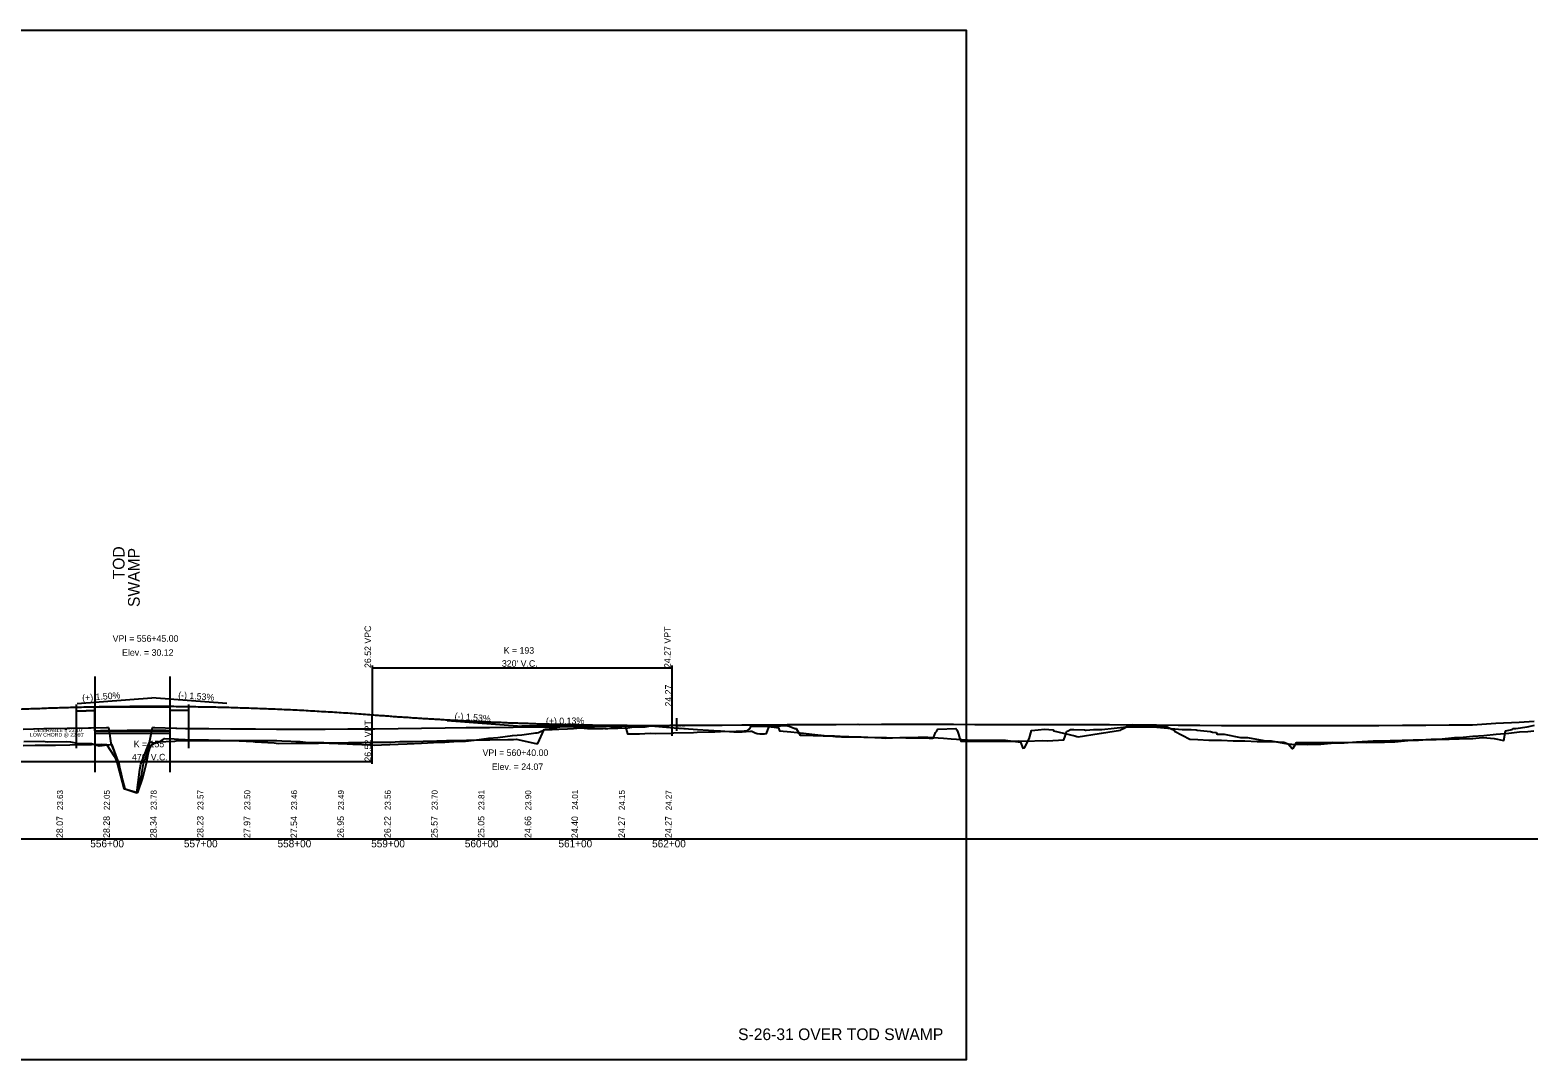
# Model space of a CAD drawing. Extents: x 2651734 to 2654815, y 758274 to 759374.
# Drawn here: x 2653205 to 2654815, y 758274 to 759374 of the extents above; entities that cross this region are included whole.
import ezdxf

# ---------------------------------------------------------------- set-up
doc = ezdxf.new("R2010")
doc.units = 0
for name, color, linetype in [('BR_CONCRETE', 7, 'Continuous'), ('BR_EXIST_GROUND_RT', 7, 'Continuous'), ('RD_EX_H2O_txCode', 7, 'Continuous'), ('RD_PD_CstnLmt', 7, 'Continuous'), ('RD_PD_DR_ErosCtrl', 7, 'Continuous'), ('RD_PD_Final_TrvlWay', 7, 'Continuous'), ('RD_PD_PaveShd', 7, 'Continuous'), ('RD_PD_RW_TX', 7, 'Continuous'), ('RD_SHT_IplotShp', 7, 'Continuous'), ('RD_SHT_ShtClip', 7, 'Continuous'), ('RD_SHT_TX', 7, 'Continuous'), ('RD_Sketch8', 7, 'Continuous')]:
    doc.layers.add(name, color=color, linetype=linetype)

msp = doc.modelspace()

# ---------------------------------------------------------------- linework, layer by layer
at = {"layer": 'BR_CONCRETE'}
for p, q in [((2653253.9, 758650.7), (2653253.9, 758646.7)), ((2653273.9, 758651.1), (2653273.9, 758625.4)), ((2653353.9, 758651.6), (2653353.9, 758625.9)), ((2653373.9, 758651.4), (2653373.9, 758647.4))]:
    msp.add_line(p, q, dxfattribs=at)
msp.add_lwpolyline([(2653197.2, 758627.3), (2653219.4, 758627.7), (2653222.2, 758627.8), (2653244.2, 758628.2), (2653247.2, 758628.2), (2653267.2, 758628.6), (2653270.1, 758628.6), (2653286.5, 758629), (2653288.5, 758629.1), (2653288.8, 758627.5), (2653291.1, 758612.1), (2653297.8, 758594.9), (2653299.3, 758590.8), (2653301.1, 758583.6), (2653305.4, 758563.5), (2653311.8, 758561.5), (2653319.2, 758559.4), (2653323.8, 758577.6), (2653325.7, 758590.5), (2653329.3, 758599.5), (2653332.2, 758612.9), (2653335.3, 758628.9), (2653338.1, 758628.9), (2653360.3, 758628.2), (2653361.4, 758628.2), (2653370.6, 758627.9), (2653393.4, 758627.8), (2653395.6, 758627.7), (2653418.6, 758627.6), (2653420.6, 758627.5), (2653443.9, 758627.4), (2653445.6, 758627.4), (2653467.9, 758627.2), (2653469.2, 758627.2), (2653470.6, 758627.2), (2653494.2, 758627.3), (2653495.3, 758627.3), (2653519.2, 758627.3), (2653520, 758627.3), (2653544.2, 758627.4), (2653544.7, 758627.4), (2653569.2, 758627.5), (2653572.9, 758627.5), (2653597.9, 758627.8), (2653622.9, 758628.2), (2653647.9, 758628.5), (2653670.5, 758628.8), (2653693.5, 758629), (2653695.5, 758629), (2653720.7, 758629.3), (2653745.5, 758629.5), (2653745.9, 758629.5), (2653769.9, 758629.7), (2653770.4, 758629.7), (2653794.9, 758630), (2653819.5, 758630.4), (2653819.9, 758630.4), (2653844.6, 758630.8), (2653844.9, 758630.8), (2653868.5, 758631.1), (2653893.2, 758631.3), (2653893.6, 758631.3), (2653918.2, 758631.5), (2653918.7, 758631.5), (2653943.2, 758631.6), (2653943.8, 758631.6), (2653964.7, 758631.8), (2653988.7, 758631.9), (2653989.7, 758631.9), (2654013.4, 758632), (2654014.7, 758632.1), (2654015.4, 758632.1), (2654038.9, 758632.2), (2654040.5, 758632.2), (2654063, 758632.3), (2654063.8, 758632.3), (2654065.6, 758632.3), (2654088.8, 758632.4), (2654090.6, 758632.3), (2654113.8, 758632.4), (2654115.6, 758632.4), (2654138.8, 758632.4), (2654140.6, 758632.4), (2654163.8, 758632.4), (2654165.5, 758632.4), (2654188.8, 758632.4), (2654190.8, 758632.4), (2654213.8, 758632.3), (2654216, 758632.3), (2654238.8, 758632.2), (2654241.1, 758632.2), (2654261.4, 758632.2), (2654264.2, 758632.2), (2654286.4, 758632.2), (2654289, 758632.2), (2654311.4, 758632.2), (2654313.8, 758632.2), (2654336.4, 758632.2), (2654338.2, 758632.2), (2654356.5, 758632.2), (2654357.4, 758632.2), (2654380.4, 758631.9), (2654382.4, 758632), (2654405.5, 758631.8), (2654405.8, 758631.8), (2654407.7, 758631.7), (2654430.8, 758631.5), (2654431.2, 758631.5), (2654433.1, 758631.5), (2654452, 758631.3), (2654453.9, 758631.3), (2654477, 758631.2), (2654478.2, 758631.2), (2654502, 758631.1), (2654502.6, 758631.1), (2654521.4, 758631.1), (2654527.1, 758631), (2654548.5, 758630.9), (2654549.2, 758630.9), (2654573.5, 758631), (2654574, 758631), (2654598.5, 758631), (2654598.9, 758631), (2654623.5, 758631.1), (2654645.2, 758631.1), (2654670.2, 758631.3), (2654695.2, 758631.5), (2654720.2, 758631.7), (2654745, 758631.9), (2654770, 758633.4), (2654794.9, 758634.8), (2654811.1, 758635.8)], dxfattribs=at)
for points, degree in [([(2653253.9, 758646.7), (2653260.6, 758646.8), (2653267.2, 758647), (2653273.9, 758647.1)], 2), ([(2653353.9, 758647.6), (2653360.6, 758647.5), (2653367.2, 758647.4), (2653373.9, 758647.4)], 2), ([(2653273.9, 758625.4), (2653274.8, 758625.5), (2653275.7, 758625.5), (2653296, 758625.8), (2653315.4, 758626), (2653341.2, 758626), (2653347.6, 758626), (2653353.9, 758625.9)], 3)]:
    msp.add_open_spline(points, degree=degree, dxfattribs=at)
at = {"layer": 'BR_EXIST_GROUND_RT'}
msp.add_lwpolyline([(2653197.9, 758614), (2653218.8, 758614.2), (2653222.9, 758613.8), (2653243.4, 758613.9), (2653247.9, 758613.5), (2653256.5, 758612), (2653270.3, 758612), (2653278.6, 758609.5), (2653281.6, 758609.8), (2653286.7, 758610.4), (2653294.5, 758598.2), (2653296.3, 758594.8), (2653297.3, 758592), (2653297.9, 758589.3), (2653304.9, 758563.6), (2653314.6, 758560.8), (2653319.7, 758559.4), (2653325, 758575.3), (2653329.2, 758591), (2653331.2, 758602.1), (2653333.6, 758610.2), (2653340.6, 758613.8), (2653359.3, 758614.3), (2653360.7, 758614.8), (2653370.5, 758615), (2653374, 758615), (2653395.3, 758615), (2653399.2, 758615), (2653420.2, 758615.1), (2653424.5, 758615), (2653445.1, 758615.1), (2653449.7, 758615), (2653467.4, 758615), (2653468.3, 758615), (2653473.6, 758614.6), (2653493.3, 758613.9), (2653498.8, 758613.4), (2653518.3, 758612.8), (2653524.1, 758612.2), (2653543.3, 758611.6), (2653549.5, 758611), (2653568.2, 758610.4), (2653569.5, 758610.3), (2653572.9, 758610.2), (2653580, 758610.5), (2653597.9, 758611.1), (2653607.5, 758611.6), (2653622.8, 758612.2), (2653635.5, 758612.9), (2653647.7, 758613.4), (2653662, 758614.2), (2653669.8, 758614.5), (2653679, 758615.4), (2653694.8, 758617.4), (2653704.3, 758618.3), (2653719.8, 758620.3), (2653729.7, 758621.1), (2653744.8, 758623.2), (2653746.4, 758623.4), (2653747.7, 758623.5), (2653755, 758627.1), (2653762.6, 758628), (2653770.1, 758629.6), (2653777.8, 758630.7), (2653791.3, 758630.1), (2653791.8, 758630.2), (2653792.8, 758629.6), (2653796.5, 758628.5), (2653818.6, 758627.9), (2653821.2, 758628), (2653821.6, 758628), (2653842.9, 758628.7), (2653847.2, 758629.2), (2653861.5, 758629.8), (2653867.6, 758630.6), (2653884.3, 758629.4), (2653892.4, 758628.7), (2653913, 758627.3), (2653917.3, 758626.9), (2653940.8, 758625.4), (2653942.2, 758625.3), (2653956.1, 758624.3), (2653965.3, 758624.3), (2653974.1, 758625.1), (2653975.4, 758625), (2653978.9, 758623.2), (2653981.1, 758622.7), (2653984.2, 758622), (2653989.2, 758622.1), (2653991.2, 758622.4), (2653993.6, 758629.2), (2653994.5, 758630.2), (2654000.3, 758630.3), (2654011.9, 758631.1), (2654015.2, 758630.5), (2654021.4, 758628), (2654022.7, 758627.8), (2654027, 758620.8), (2654030.4, 758620.7), (2654051.8, 758620.2), (2654054.8, 758620.1), (2654063.7, 758619.9), (2654069.8, 758619.7), (2654088.7, 758618.9), (2654092.1, 758618.8), (2654113.8, 758617.8), (2654114.3, 758617.8), (2654118.3, 758617.6), (2654133.7, 758618.1), (2654138.8, 758618.2), (2654153.1, 758618.5), (2654163.4, 758618.7), (2654180.3, 758617.5), (2654188.3, 758617), (2654211.5, 758615.3), (2654213.3, 758615.3), (2654235.7, 758615.3), (2654238.3, 758615.3), (2654243.2, 758615.4), (2654246.3, 758615.4), (2654262.4, 758613.4), (2654265, 758606.7), (2654266.7, 758607.2), (2654271.5, 758616.8), (2654274.3, 758625.7), (2654281.3, 758626.5), (2654288.2, 758627.1), (2654297.3, 758626.5), (2654297.7, 758625.5), (2654320.3, 758619.9), (2654322.6, 758619.3), (2654323.9, 758619), (2654346.4, 758622.5), (2654348.8, 758622.9), (2654369.2, 758626.1), (2654369.8, 758626.7), (2654373.1, 758628.3), (2654375.9, 758629.9), (2654384.2, 758630), (2654394.1, 758631.3), (2654396.7, 758631.4), (2654403.3, 758630.6), (2654417.4, 758630), (2654418.2, 758630), (2654422.7, 758627.9), (2654426.6, 758626.1), (2654426.9, 758625), (2654443.3, 758616.5), (2654451.9, 758616), (2654463.7, 758615.5), (2654476.9, 758615.4), (2654489.4, 758614.8), (2654501.9, 758614.7), (2654515.3, 758614.1), (2654526.9, 758614), (2654532, 758613.9), (2654543.5, 758613.3), (2654548.2, 758611.5), (2654552.5, 758606.5), (2654553.2, 758606.5), (2654553.6, 758606.9), (2654557.2, 758612.8), (2654569.8, 758613), (2654582.2, 758612.8), (2654595.3, 758613.1), (2654607.1, 758612.9), (2654620.7, 758613.2), (2654632, 758613), (2654643.5, 758613.2), (2654651.1, 758613.1), (2654662.1, 758613.6), (2654676.1, 758614.9), (2654687.4, 758615.4), (2654701, 758616.6), (2654712.7, 758617), (2654726, 758618.2), (2654735.3, 758618.6), (2654745.4, 758619.5), (2654757.3, 758620.4), (2654770.4, 758621.9), (2654783.8, 758622.9), (2654795.4, 758624.2), (2654804.1, 758624.8), (2654810.5, 758625.5)], dxfattribs=at)
at = {"layer": 'RD_EX_H2O_txCode'}
msp.add_line((2651814.9, 758509.9), (2654814.9, 758509.9), dxfattribs=at)
at = {"layer": 'RD_PD_DR_ErosCtrl'}
for points in [[(2653099.9, 758643), (2653109.3, 758643.7), (2653118.7, 758644.3), (2653128.1, 758644.9), (2653137.5, 758645.5), (2653146.9, 758646.1), (2653156.3, 758646.7), (2653165.7, 758647.2), (2653175.1, 758647.7), (2653184.5, 758648.1), (2653193.9, 758648.6), (2653203.3, 758649), (2653212.7, 758649.3), (2653222.1, 758649.7), (2653231.5, 758650), (2653240.9, 758650.3), (2653250.3, 758650.6), (2653259.7, 758650.8), (2653269.1, 758651), (2653278.5, 758651.2), (2653287.9, 758651.3), (2653297.3, 758651.4), (2653306.7, 758651.5), (2653316.1, 758651.6), (2653325.5, 758651.6), (2653334.9, 758651.6), (2653344.3, 758651.6), (2653353.7, 758651.6), (2653363.1, 758651.5), (2653372.5, 758651.4), (2653381.9, 758651.2), (2653391.3, 758651.1), (2653400.7, 758650.9), (2653410.1, 758650.7), (2653419.5, 758650.4), (2653428.9, 758650.1), (2653438.3, 758649.8), (2653447.7, 758649.5), (2653457.1, 758649.1), (2653466.5, 758648.7), (2653475.9, 758648.3), (2653485.3, 758647.9), (2653494.7, 758647.4), (2653504.1, 758646.9), (2653513.5, 758646.3), (2653522.9, 758645.8), (2653532.3, 758645.2), (2653541.7, 758644.6), (2653551.1, 758643.9), (2653560.5, 758643.2), (2653569.9, 758642.5)], [(2653569.9, 758642.5), (2653576.3, 758642), (2653582.7, 758641.6), (2653589.1, 758641.1), (2653595.5, 758640.6), (2653601.9, 758640.2), (2653608.3, 758639.8), (2653614.7, 758639.3), (2653621.1, 758638.9), (2653627.5, 758638.5), (2653633.9, 758638.1), (2653640.3, 758637.8), (2653646.7, 758637.4), (2653653.1, 758637), (2653659.5, 758636.7), (2653665.9, 758636.4), (2653672.3, 758636), (2653678.7, 758635.7), (2653685.1, 758635.4), (2653691.5, 758635.1), (2653697.9, 758634.8), (2653704.3, 758634.6), (2653710.7, 758634.3), (2653717.1, 758634), (2653723.5, 758633.8), (2653729.9, 758633.6), (2653736.3, 758633.4), (2653742.7, 758633.1), (2653749.1, 758632.9), (2653755.5, 758632.8), (2653761.9, 758632.6), (2653768.3, 758632.4), (2653774.7, 758632.3), (2653781.1, 758632.1), (2653787.5, 758632), (2653793.9, 758631.9), (2653800.3, 758631.7), (2653806.7, 758631.6), (2653813.1, 758631.5), (2653819.5, 758631.5), (2653825.9, 758631.4), (2653832.3, 758631.3), (2653838.7, 758631.3), (2653845.1, 758631.2), (2653851.5, 758631.2), (2653857.9, 758631.2), (2653864.3, 758631.2), (2653870.7, 758631.2), (2653877.1, 758631.2), (2653883.5, 758631.2), (2653889.9, 758631.3)]]:
    msp.add_spline(points, degree=3, dxfattribs=at)
at = {"layer": 'RD_PD_RW_TX'}
msp.add_lwpolyline([(2653197.3, 758609.8), (2653210.3, 758610), (2653222.3, 758610.1), (2653231.9, 758610.2), (2653247.3, 758610.4), (2653260.3, 758610.6), (2653270.4, 758610.7), (2653281.3, 758611.1), (2653292, 758610.4), (2653298.6, 758592.9), (2653299.3, 758592.9), (2653301, 758581.9), (2653305.8, 758563.4), (2653309.1, 758562.3), (2653318.7, 758559.3), (2653322, 758584.1), (2653323, 758589.6), (2653324.2, 758592.7), (2653332.4, 758613.3), (2653336.6, 758612.5), (2653342.6, 758613.2), (2653348.2, 758617.2), (2653358.7, 758617), (2653368.1, 758616.2), (2653370.2, 758616.2), (2653392.3, 758615.7), (2653395.2, 758615.6), (2653420.1, 758615), (2653420.7, 758615), (2653443.1, 758614), (2653445.2, 758613.7), (2653465.4, 758612.7), (2653469.8, 758612), (2653488.6, 758612.1), (2653494.8, 758612.2), (2653512.7, 758612.3), (2653519.8, 758612.5), (2653536.8, 758612.6), (2653544.8, 758612.8), (2653560.8, 758612.9), (2653569.9, 758613.2), (2653572.5, 758613.2), (2653574.5, 758613.3), (2653589.5, 758613.4), (2653599.5, 758613.9), (2653614.3, 758614), (2653624.5, 758614.4), (2653639.1, 758614.6), (2653649.5, 758615), (2653662.3, 758615.1), (2653670.7, 758615.5), (2653684.3, 758615.7), (2653695.6, 758615.9), (2653714.8, 758616.1), (2653720.3, 758616.2), (2653720.9, 758616.2), (2653723.9, 758616.3), (2653744.7, 758611.7), (2653746.5, 758611.9), (2653746.9, 758611.8), (2653753.7, 758626.7), (2653756.9, 758626.9), (2653762.2, 758626.7), (2653769.5, 758627.1), (2653778.5, 758627.4), (2653785, 758627.7), (2653792.4, 758628.5), (2653799.9, 758628), (2653806.4, 758627.8), (2653816.9, 758628), (2653823.9, 758628.1), (2653826.6, 758629), (2653829.1, 758629.5), (2653840.2, 758630.6), (2653842.7, 758622.1), (2653843.3, 758622), (2653855.5, 758622.2), (2653867.1, 758622.8), (2653872.5, 758622.6), (2653890.4, 758623), (2653892.1, 758623.1), (2653913.3, 758623.6), (2653917.2, 758623.8), (2653936.1, 758624.3), (2653942.2, 758624.6), (2653958.9, 758625.1), (2653967.2, 758625.5), (2653967.9, 758625.5), (2653970.7, 758625.6), (2653972.8, 758627.1), (2653974, 758629.4), (2653974.3, 758629.9), (2653974.6, 758630.5), (2653980, 758630.5), (2653990.1, 758630.3), (2653999.4, 758629.3), (2654003.8, 758628.5), (2654005.1, 758625.4), (2654017.2, 758624.2), (2654030.6, 758622.8), (2654039.7, 758621.9), (2654056, 758620.2), (2654059.1, 758619.9), (2654065, 758619.3), (2654071.2, 758619), (2654090, 758618.8), (2654095.2, 758618.5), (2654115.1, 758618.3), (2654119.3, 758618.1), (2654140.1, 758617.9), (2654143.4, 758617.8), (2654165, 758617.6), (2654168.6, 758617.6), (2654169.4, 758617.9), (2654171.7, 758623.5), (2654172.9, 758625), (2654173.3, 758626.7), (2654174.1, 758627.3), (2654174.6, 758627.3), (2654193.2, 758627.7), (2654194.3, 758626.6), (2654195.4, 758623.9), (2654196.1, 758621.8), (2654197.5, 758616.7), (2654198.7, 758614.2), (2654218.6, 758614.2), (2654224, 758614.3), (2654240.9, 758614.3), (2654249.2, 758614.5), (2654256.8, 758614.5), (2654260.5, 758614.6), (2654269.6, 758614.3), (2654285.5, 758615), (2654291.4, 758614.8), (2654308.7, 758615.9), (2654310.1, 758619.5), (2654311.3, 758623.4), (2654311.6, 758624.5), (2654313.3, 758625.4), (2654315.7, 758626.8), (2654319.2, 758626.8), (2654330.6, 758626.3), (2654331.9, 758626.2), (2654332.4, 758626.2), (2654340.4, 758626.8), (2654349.2, 758626.8), (2654375.7, 758629.5), (2654380.3, 758629.8), (2654404, 758629.7), (2654435.1, 758626.7), (2654444.5, 758626.7), (2654449.9, 758626.6), (2654451.2, 758626.2), (2654458.3, 758625.2), (2654465.3, 758624.5), (2654467.6, 758623.8), (2654471.2, 758623.7), (2654472.4, 758621.9), (2654479.9, 758621.7), (2654497.4, 758618.4), (2654505, 758618.1), (2654522.4, 758614.9), (2654530.1, 758614.6), (2654547.4, 758611.5), (2654548.1, 758611.4), (2654549.1, 758611.2), (2654552.1, 758611.1), (2654568.8, 758610.8), (2654577.7, 758611.2), (2654583.1, 758611.1), (2654597.6, 758612.4), (2654608.1, 758612.7), (2654621.2, 758613.8), (2654633.2, 758614.2), (2654639, 758614.7), (2654645.1, 758614.8), (2654657.1, 758615), (2654670.1, 758615.4), (2654681.8, 758615.6), (2654695.1, 758616), (2654706.4, 758616.2), (2654720.1, 758616.6), (2654730.9, 758616.7), (2654745.4, 758617.2), (2654755.5, 758618.2), (2654760.4, 758617.8), (2654768.2, 758617.1), (2654778.5, 758615.2), (2654780.4, 758625.3), (2654787.4, 758626.9), (2654789, 758627.7), (2654791.3, 758628), (2654803.4, 758629.5), (2654805.2, 758629.9), (2654811.5, 758631.5)], dxfattribs=at)
at = {"layer": 'RD_SHT_IplotShp'}
for p, q in [((2653255.1, 758654.6), (2653334.9, 758660.5)), ((2653414.7, 758654.4), (2653334.9, 758660.5)), ((2653650.1, 758636.4), (2653729.9, 758630.3)), ((2653809.9, 758630.8), (2653729.9, 758630.3))]:
    msp.add_line(p, q, dxfattribs=at)
at = {"layer": 'RD_SHT_ShtClip'}
for p, q in [((2653273.9, 758683.5), (2653273.9, 758581.1)), ((2653353.9, 758683.5), (2653353.9, 758581.1)), ((2653253.9, 758653.5), (2653253.9, 758606.8)), ((2653273.9, 758625.4), (2653273.9, 758651.1)), ((2653273.9, 758651.1), (2653353.9, 758651.1)), ((2653353.9, 758651.1), (2653353.9, 758625.4)), ((2653373.9, 758653.5), (2653373.9, 758606.8)), ((2653889.9, 758643.7), (2653889.9, 758620)), ((2653889.9, 758631.3), (2653894.9, 758631.3)), ((2653894.9, 758638.9), (2653894.9, 758625.2)), ((2653273.9, 758625.4), (2653353.9, 758625.4)), ((2653273.9, 758622.9), (2653353.9, 758622.9))]:
    msp.add_line(p, q, dxfattribs=at)
msp.add_lwpolyline([(2652404.5, 759373.9), (2654204.5, 759373.9), (2654204.5, 758273.9), (2652404.5, 758273.9)], close=True, dxfattribs=at)
at = {"layer": 'RD_Sketch8'}
for p, q in [((2653569.9, 758695), (2653569.9, 758642.5)), ((2653569.9, 758692.5), (2653889.9, 758692.5)), ((2653889.9, 758695), (2653889.9, 758631.3)), ((2653569.9, 758590), (2653569.9, 758642.5)), ((2653099.9, 758592.5), (2653569.9, 758592.5))]:
    msp.add_line(p, q, dxfattribs=at)

# ---------------------------------------------------------------- texts
at = {"layer": 'RD_PD_CstnLmt'}
for s, p in [('556+00', (2653269, 758500.9)), ('557+00', (2653369, 758500.9)), ('558+00', (2653469, 758500.9)), ('559+00', (2653569, 758500.9)), ('560+00', (2653669, 758500.9)), ('561+00', (2653769, 758500.9)), ('562+00', (2653869, 758500.9))]:
    msp.add_text(s, height=8, dxfattribs=at).set_placement(p)
at = {"layer": 'RD_PD_Final_TrvlWay'}
for s, height, p in [('26.52 VPC', 7, (2653568.9, 758692.5)), ('24.27 VPT', 7, (2653888.9, 758692.5)), ('26.52 VPT', 7, (2653568.9, 758592.5)), ('23.63', 6.4, (2653239.9, 758540.7)), ('22.05', 6.4, (2653289.9, 758540.7)), ('23.78', 6.4, (2653339.9, 758540.7)), ('23.57', 6.4, (2653389.9, 758540.7)), ('23.50', 6.4, (2653439.9, 758540.7)), ('23.46', 6.4, (2653489.9, 758540.7)), ('23.49', 6.4, (2653539.9, 758540.7)), ('23.56', 6.4, (2653589.9, 758540.7)), ('23.70', 6.4, (2653639.9, 758540.7)), ('23.81', 6.4, (2653689.9, 758540.7)), ('23.90', 6.4, (2653739.9, 758540.5)), ('24.01', 6.4, (2653789.9, 758541)), ('24.15', 6.4, (2653839.9, 758540.7)), ('24.27', 6.4, (2653889.9, 758540.5)), ('28.07', 7, (2653239.9, 758510.9)), ('28.28', 7, (2653289.9, 758511)), ('28.34', 7, (2653339.9, 758510.8)), ('28.23', 7, (2653389.9, 758511.1)), ('27.97', 7, (2653439.9, 758510.9)), ('27.54', 7, (2653489.9, 758510.8)), ('26.95', 7, (2653539.9, 758511)), ('26.22', 7, (2653589.9, 758510.9)), ('25.57', 7, (2653639.9, 758510.9)), ('25.05', 7, (2653689.9, 758511)), ('24.66', 7, (2653739.9, 758510.9)), ('24.40', 7, (2653789.9, 758510.8)), ('24.27', 7, (2653839.9, 758510.9)), ('24.27', 7, (2653889.9, 758510.9))]:
    msp.add_text(s, height=height, rotation=90, dxfattribs=at).set_placement(p)
at = {"layer": 'RD_PD_PaveShd'}
for s, p in [('VPI = 556+45.00', (2653292.9, 758720.5)), ('Elev. = 30.12', (2653303, 758705.5)), ('VPI = 560+40.00', (2653687.9, 758598.5)), ('Elev. = 24.07', (2653697.8, 758583.5))]:
    msp.add_text(s, height=7, dxfattribs=at).set_placement(p)
msp.add_text('24.27', height=7, rotation=90, dxfattribs=at).set_placement((2653889.9, 758651.3))
at = {"layer": 'RD_SHT_IplotShp'}
for s, rotation, p in [('(+) 1.50%', 4.2749, (2653260.6, 758657)), ('(-) 1.53%', 355.6173, (2653362.7, 758660.4)), ('(-) 1.53%', 355.6173, (2653657.9, 758637.8)), ('(+) 0.13%', 0.361, (2653755.6, 758632.4))]:
    msp.add_text(s, height=7, rotation=rotation, dxfattribs=at).set_placement(p)
at = {"layer": 'RD_SHT_ShtClip'}
for s, height, p in [('+0.1260', 2, (2653895, 758629)), ("LOW CHORD @ 22.60'", 4, (2653204.6, 758619.2)), ("DESIRABLE = 23.10'", 4, (2653208.8, 758624))]:
    msp.add_text(s, height=height, dxfattribs=at).set_placement(p)
at = {"layer": 'RD_SHT_TX'}
for s, height, rotation, p in [('TOD', 12.5, 90, (2653305.6, 758787.2)), (' SWAMP', 12.5, 90, (2653321.8, 758753)), ('S-26-31 OVER TOD SWAMP', 12.499, 360, (2653960.8, 758295))]:
    msp.add_text(s, height=height, rotation=rotation, dxfattribs=at).set_placement(p)
at = {"layer": 'RD_Sketch8'}
for s, p in [('K = 193', (2653710.5, 758707.8)), ("320' V.C.", (2653708.6, 758693.8)), ('K = 155', (2653315.4, 758607.8)), ("470' V.C.", (2653313.6, 758593.8))]:
    msp.add_text(s, height=7, dxfattribs=at).set_placement(p)

doc.saveas('drawing.dxf')
